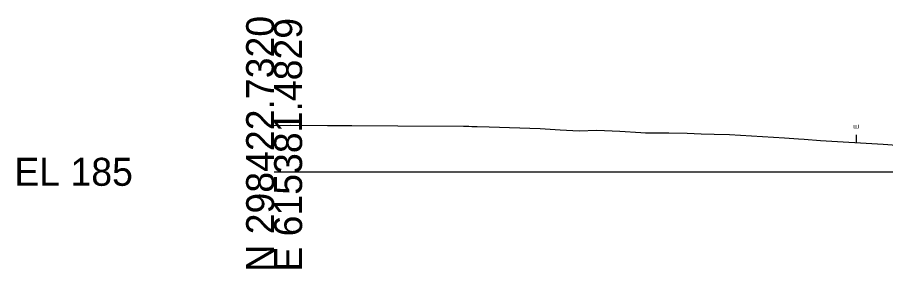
# Model space of a CAD drawing. Extents: x 517327 to 517505, y 114839 to 117370.
# Drawn here: x 517326.7 to 517413.6, y 115838.7 to 115863.8 of the extents above; entities that cross this region are included whole.
import ezdxf

# ---------------------------------------------------------------- set-up
doc = ezdxf.new("R2010")
doc.units = 0
for name, color, linetype in [('Exist XS Ground Line', 7, 'Continuous'), ('Old_Level_63', 7, 'Continuous'), ('Prop XS Exc Vertical Line 1', 7, 'Continuous')]:
    doc.layers.add(name, color=color, linetype=linetype)

msp = doc.modelspace()

# ---------------------------------------------------------------- linework, layer by layer
at = {"layer": 'Exist XS Ground Line'}
for p, q in [((517352.365, 115853.011), (517353.99, 115853.02)), ((517353.99, 115853.02), (517357.707, 115853.016)), ((517357.707, 115853.016), (517360.144, 115852.985)), ((517360.144, 115852.985), (517364.752, 115852.984)), ((517364.752, 115852.984), (517371.321, 115852.926)), ((517371.321, 115852.926), (517371.839, 115852.923)), ((517371.839, 115852.923), (517372.143, 115852.912)), ((517372.143, 115852.912), (517372.685, 115852.895)), ((517372.685, 115852.895), (517373.877, 115852.855)), ((517373.877, 115852.855), (517378.978, 115852.704)), ((517378.978, 115852.704), (517380.979, 115852.566)), ((517380.979, 115852.566), (517382.89, 115852.482)), ((517382.89, 115852.482), (517384.643, 115852.526)), ((517384.643, 115852.526), (517386.942, 115852.442)), ((517386.942, 115852.442), (517389.067, 115852.299)), ((517389.067, 115852.299), (517389.528, 115852.279)), ((517389.528, 115852.279), (517390.253, 115852.268)), ((517390.253, 115852.268), (517391.849, 115852.255)), ((517391.849, 115852.255), (517393.7, 115852.234)), ((517393.7, 115852.234), (517395.092, 115852.183)), ((517395.092, 115852.183), (517396.382, 115852.138)), ((517396.382, 115852.138), (517397.928, 115852.098)), ((517397.928, 115852.098), (517403.449, 115851.761)), ((517403.449, 115851.761), (517404.845, 115851.668)), ((517404.845, 115851.668), (517405.388, 115851.634)), ((517405.388, 115851.634), (517407.029, 115851.512)), ((517407.029, 115851.512), (517413.306, 115851.146)), ((517413.306, 115851.146), (517417.054, 115850.824))]:
    msp.add_line(p, q, dxfattribs=at)
at = {"layer": 'Old_Level_63'}
msp.add_line((517352.365, 115848.365), (517427.365, 115848.365), dxfattribs=at)
at = {"layer": 'Prop XS Exc Vertical Line 1'}
msp.add_line((517410.601, 115852.054), (517410.601, 115851.304), dxfattribs=at)

# ---------------------------------------------------------------- texts
at = {"layer": 'Old_Level_63'}
for s, p in [('N 298422.7320', (517352.365, 115838.365)), ('E 615381.4829', (517355.165, 115838.365))]:
    msp.add_text(s, height=2.8, rotation=90, dxfattribs=at).set_placement(p)
msp.add_text('EL 185', height=2.8, dxfattribs=at).set_placement((517326.366, 115846.965))
at = {"layer": 'Prop XS Exc Vertical Line 1'}
msp.add_text('E', height=0.5, rotation=90, dxfattribs=at).set_placement((517410.851, 115852.646))

doc.saveas('drawing.dxf')
